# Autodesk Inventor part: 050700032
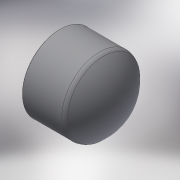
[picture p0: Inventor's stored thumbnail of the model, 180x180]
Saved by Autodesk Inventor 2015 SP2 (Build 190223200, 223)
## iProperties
Created: 2017-10
Part Number: 050700032
Material: Generic
Description: PLASSON CAP-CEMENT PVC 32
Document SubType Name: Modeling
Designer: KIM
Density: 1 g/cm^3
Appearance: Default
Author: KIM
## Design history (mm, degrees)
derived "050700.ipt"
feature "Solid1::050700.ipt"
tag "TaggingFeature1"
body "Solid1"
other parameters: "d7" = 0.32, "d9" = 38, "d28" = 1, "d29" = 22, "d30" = 32, "d31" = 28.8, "d32" = 32, "d33" = 23.1, "d34" = 3.2, "d_" = 32, "E_" = 38, "H_" = 32, "l_" = 22
